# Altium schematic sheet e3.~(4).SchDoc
size custom portrait; Address1: Address1; Address2: Address2; Address3: Address3; Address4: Address4; SheetNumber: 1; SheetTotal: 1; Scale: 1:1; Разраб.: Иванов; Обозначение документа: АБВГ.123456.001Э3; Пров.: Петров; Утв.: Сидоров; Наименование организации: ОАО "Ваша фирма"; Перв. применение: АБВГ.123456.000; Наименование изделия 1: Плата; Наименование изделия 2: Схема электрическая; Наименование изделия 3: принципиальная; Нач. отд.: Нач. отд.; Фамилия нач. отд.: Сидоров
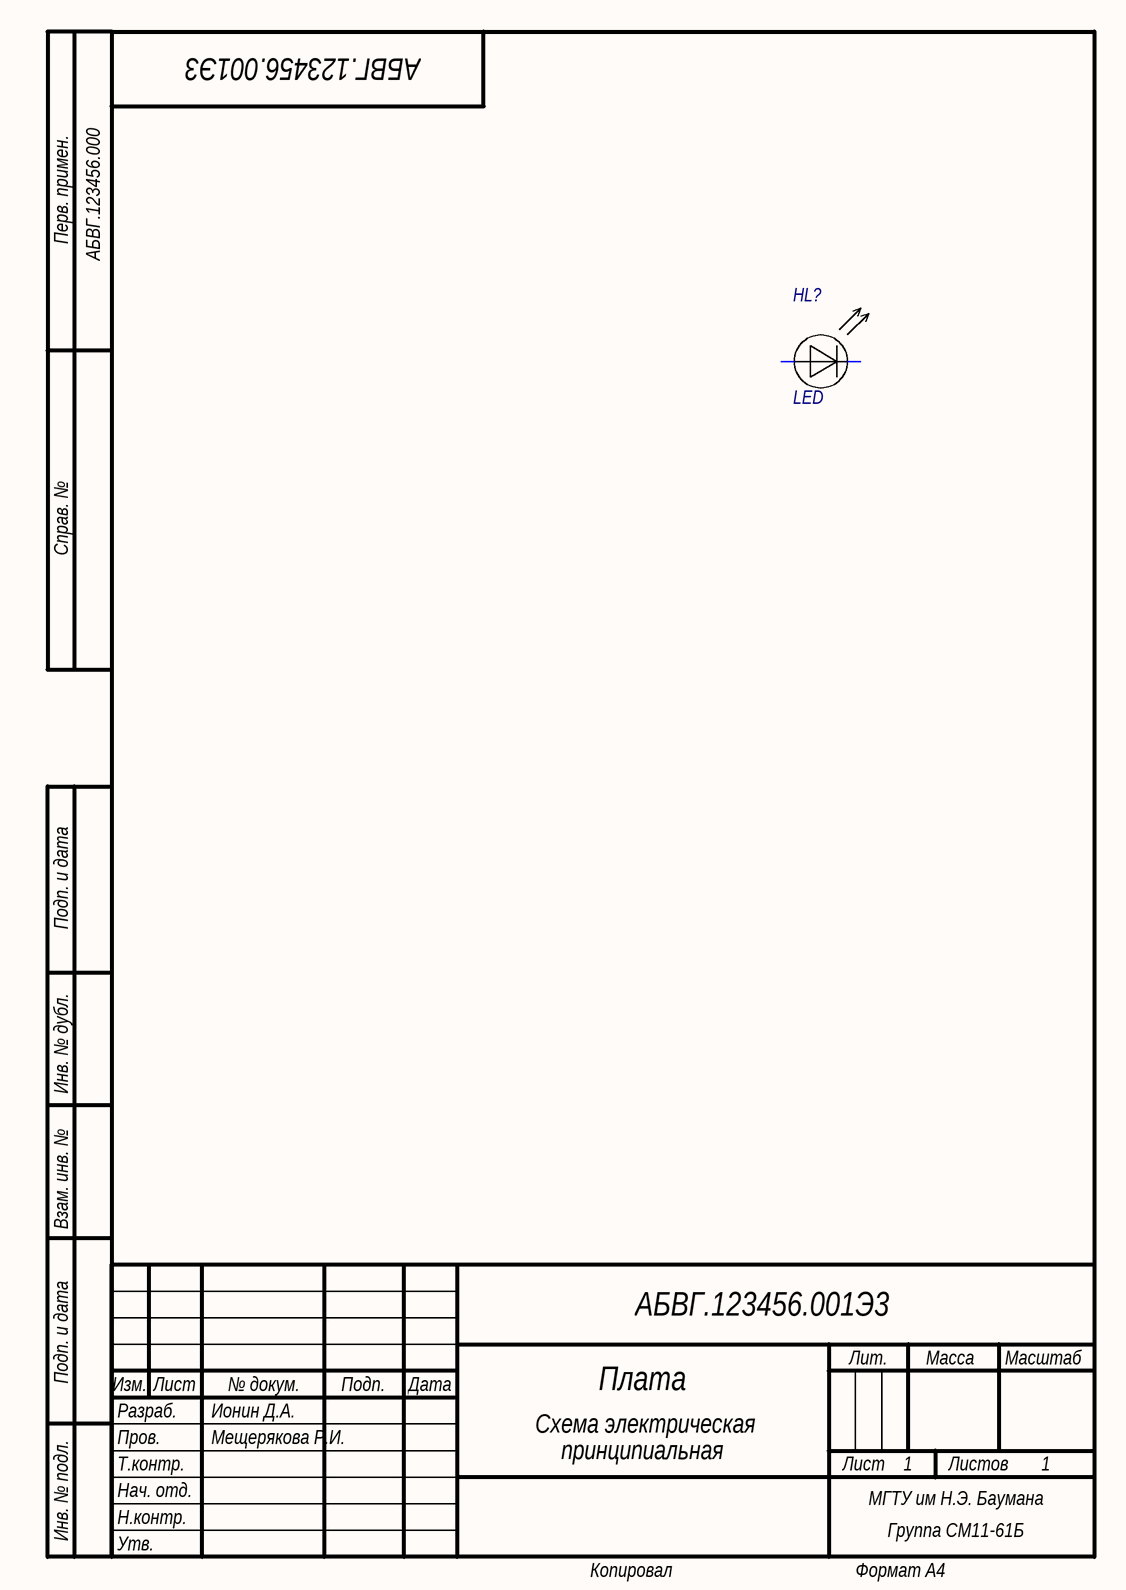
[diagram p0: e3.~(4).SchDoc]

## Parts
HL?  LED

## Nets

Not connected (* = marked no-connect by the designer): HL? 1 2

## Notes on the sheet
- Перв. примен.
- Справ. №
- Подп. и дата
- Инв. № дубл.
- Взам. инв. №
- Разраб.
- Изм.
- Лист
- Ионин Д.А.
- № докум.
- Подп.
- Дата
- Лит.
- Масса
- Масштаб
- Пров.
- Т.контр.
- Мещерякова Р.И.
- Листов
- Инв. № подл.
- Утв.
- Н.контр.
- МГТУ им Н.Э. Баумана
- Группа СМ11-61Б
- Копировал
- Формат А4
